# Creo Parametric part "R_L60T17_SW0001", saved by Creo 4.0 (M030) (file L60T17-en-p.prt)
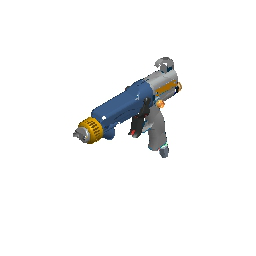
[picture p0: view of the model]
Units: Inch lbm Second (Pro/E Default); INCH, POUND, SECS

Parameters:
  COPY_GEOM_ORIGIN_TYPE = "Part"

Created from: INLBS_PART_SOLID.PRT

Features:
  1. datum plane "RIGHT"
  2. datum plane "TOP"
  3. datum plane "FRONT"
  4. coordinate system
  5. feature "Extern Copy Geom id 41"
  6. feature "Extern Copy Geom id 2042"
  7. feature "Extern Copy Geom id 2061"
  8. feature "Extern Copy Geom id 2102"
  9. feature "Extern Copy Geom id 2173"
  10. feature "Extern Copy Geom id 2186"
  11. feature "Extern Copy Geom id 2565"
  12. feature "Extern Copy Geom id 2796"
  13. feature "Extern Copy Geom id 2809"
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
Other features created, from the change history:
  feature "Extern Copy Geom id 4145"
  feature "Extern Copy Geom id 4236"
  feature "Extern Copy Geom id 4261"
  feature "Extern Copy Geom id 4286"
  feature "Extern Copy Geom id 5638"
  feature "Extern Copy Geom id 6046"
  feature "Extern Copy Geom id 6059"
  feature "Extern Copy Geom id 6075"
  feature "Extern Copy Geom id 6106"
  feature "Extern Copy Geom id 6181"
  feature "Extern Copy Geom id 6275"
  feature "Extern Copy Geom id 6428"
  feature "Extern Copy Geom id 6434"
  feature "Extern Copy Geom id 6488"
  feature "Extern Copy Geom id 6510"
  feature "Extern Copy Geom id 6759"
  feature "Extern Copy Geom id 6782"
  feature "Extern Copy Geom id 8225"
  feature "Extern Copy Geom id 8238"
  feature "Extern Copy Geom id 8251"
  feature "Extern Copy Geom id 8265"
  feature "Extern Copy Geom id 8290"
  feature "Extern Copy Geom id 8315"
  feature "Extern Copy Geom id 8393"
  feature "Extern Copy Geom id 9377"
  feature "Extern Copy Geom id 9398"
  feature "Extern Copy Geom id 9486"
  feature "Extern Copy Geom id 10693"
  feature "Extern Copy Geom id 10713"
  feature "Extern Copy Geom id 10727"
